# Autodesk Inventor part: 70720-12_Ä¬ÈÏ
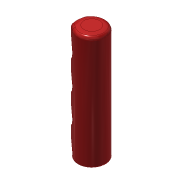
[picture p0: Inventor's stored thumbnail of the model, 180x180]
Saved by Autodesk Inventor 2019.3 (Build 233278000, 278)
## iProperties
Created: 2010-06
Part Number: 70720-12_Ä¬ÈÏ
Material: Ogólny
Document SubType Name: Modeling
Designer: CADENGINEERING4
Density: 1 g/cm^3
Appearance: Jasnoczerwona
Author: CADENGINEERING4
Revision Number: ÈÎºÎ
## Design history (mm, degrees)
feature "NONE"
node "Bryła1"
